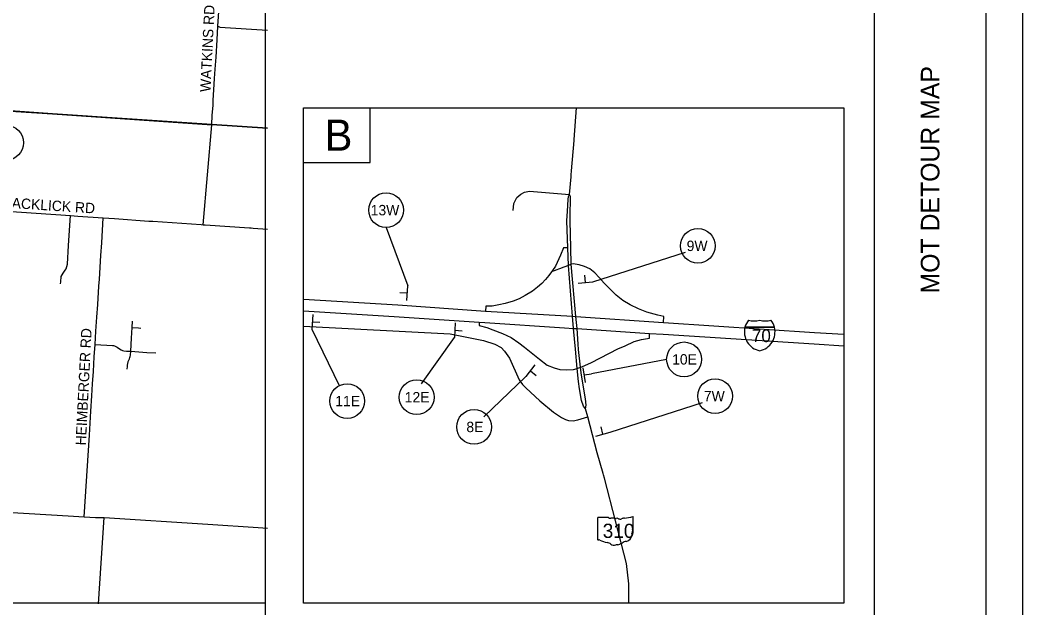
# Model space of a CAD drawing. Extents: x 1880545 to 1948545, y 79309 to 723051.
# Drawn here: x 1921540 to 1948545, y 691027 to 706870 of the extents above; entities that cross this region are included whole.
import ezdxf

# ---------------------------------------------------------------- set-up
doc = ezdxf.new("R2010")
doc.units = 0
for name, color, linetype in [('GM_X_County', 7, 'Continuous'), ('GM_X_County_Road', 7, 'Continuous'), ('GM_X_Interchange_Ramps', 7, 'Continuous'), ('GM_X_Interstate_Route', 7, 'Continuous'), ('GM_X_Interstate_Shield', 7, 'Continuous'), ('GM_X_State_Route', 7, 'Continuous'), ('GM_X_State_Shield', 7, 'Continuous'), ('GM_X_Township', 7, 'Continuous'), ('GM_X_Township_Road', 7, 'Continuous'), ('SH_Border', 7, 'Continuous'), ('SH_Cut_Line', 7, 'Continuous'), ('SH_Data', 7, 'Continuous'), ('SH_Text', 7, 'Continuous')]:
    doc.layers.add(name, color=color, linetype=linetype)

msp = doc.modelspace()

# ---------------------------------------------------------------- linework, layer by layer
at = {"layer": 'GM_X_County'}
msp.add_lwpolyline([(1921285, 704420), (1922414, 704344), (1926703, 704052), (1928206, 703952)], dxfattribs=at)
at = {"layer": 'GM_X_County_Road'}
for points in [[(1926867, 706707), (1926885, 706967), (1927000, 708778), (1927002, 708804)], [(1926704, 704049), (1926716, 704303), (1926736, 704569), (1926742, 704707), (1926762, 704992), (1926780, 705293), (1926797, 705544), (1926819, 705870), (1926849, 706332), (1926867, 706707)], [(1918344, 701901), (1920647, 701753), (1922902, 701601), (1923097, 701588), (1923778, 701542), (1924079, 701522), (1925008, 701454), (1925058, 701452), (1925112, 701448), (1926417, 701359), (1926469, 701355), (1926521, 701352), (1927717, 701271), (1927760, 701268), (1927820, 701264), (1928206, 701237)]]:
    msp.add_lwpolyline(points, dxfattribs=at)
at = {"layer": 'GM_X_Interchange_Ramps'}
for points in [[(1936289, 700732), (1936172, 700733), (1936094, 700533), (1935957, 700241), (1935879, 700117), (1935780, 699982), (1935689, 699875), (1935588, 699772), (1935470, 699667), (1935336, 699567), (1935137, 699445), (1934975, 699360), (1934821, 699294), (1934601, 699227), (1934428, 699194), (1934256, 699163), (1934079, 699159), (1934073, 699027)], [(1936384, 700292), (1936307, 700258), (1936183, 700212), (1936065, 700169), (1935970, 700132), (1935905, 700102), (1935879, 700117)], [(1938865, 698717), (1938871, 698882), (1938712, 698918), (1938417, 698999), (1938189, 699088), (1937965, 699195), (1937768, 699312), (1937589, 699455), (1937271, 699782), (1937132, 699936), (1937016, 700058), (1936886, 700162), (1936738, 700230), (1936597, 700270), (1936431, 700299), (1936384, 700292)], [(1933904, 698726), (1933898, 698642), (1934113, 698582), (1934268, 698520), (1934532, 698426), (1934760, 698314), (1934970, 698175), (1935123, 698054)], [(1936627, 697514), (1936663, 697527), (1936927, 697645), (1937634, 698006), (1937836, 698091), (1938079, 698207), (1938271, 698260), (1938485, 698301), (1938493, 698422)], [(1935123, 698054), (1935529, 697732), (1935735, 697567), (1935925, 697496), (1936075, 697455), (1936247, 697444), (1936445, 697457), (1936540, 697478), (1936627, 697514)]]:
    msp.add_lwpolyline(points, dxfattribs=at)
at = {"layer": 'GM_X_Interstate_Route'}
for points in [[(1929171, 699347), (1931715, 699191), (1934073, 699027), (1936416, 698889), (1936506, 698883), (1938865, 698717), (1942936, 698453), (1943726, 698404)], [(1929171, 699033), (1931612, 698884), (1933904, 698726), (1934059, 698717), (1936199, 698576)], [(1936199, 698576), (1936444, 698560), (1936540, 698554), (1938493, 698422), (1938854, 698403), (1942925, 698140), (1943726, 698088)]]:
    msp.add_lwpolyline(points, dxfattribs=at)
at = {"layer": 'GM_X_Interstate_Shield'}
for p, q in [((1941060, 698592), (1941853, 698592)), ((1941853, 698592), (1941060, 698592)), ((1941853, 698592), (1941060, 698592))]:
    msp.add_line(p, q, dxfattribs=at)
for centre, start, end in [((1941560, 698465), 141.669, 165.8066), ((1941306, 699278), 253.0091, 286.9909), ((1941607, 699278), 253.0091, 286.9909), ((1941353, 698465), 14.1934, 38.331), ((1941560, 698465), 165.8066, 258.463), ((1941353, 698465), 281.537, 14.1934)]:
    msp.add_arc(centre, 516, start, end, dxfattribs=at)
at = {"layer": 'GM_X_State_Route'}
for p, q in [((1936393, 702809), (1936461, 703622)), ((1936339, 702169), (1936380, 702648)), ((1936826, 696180), (1936768, 696393)), ((1937249, 694616), (1937240, 694646))]:
    msp.add_line(p, q, dxfattribs=at)
for points in [[(1936461, 703622), (1936463, 703655), (1936519, 704501)], [(1936380, 702648), (1936384, 702696), (1936393, 702809)], [(1936540, 697478), (1936492, 698002), (1936444, 698560), (1936416, 698889), (1936307, 700258), (1936289, 700732), (1936267, 701463), (1936279, 701716), (1936296, 702031), (1936308, 702111), (1936339, 702169)], [(1936570, 698134), (1936540, 698554), (1936506, 698883), (1936384, 700292), (1936368, 700730), (1936352, 701461), (1936354, 701698), (1936365, 701967), (1936359, 702111), (1936339, 702169)], [(1936627, 697514), (1936580, 697994), (1936570, 698134)], [(1936768, 696393), (1936714, 696466), (1936662, 696620), (1936604, 696936), (1936575, 697129), (1936540, 697478)], [(1936768, 696393), (1936780, 696490), (1936766, 696664), (1936709, 696980), (1936650, 697365), (1936627, 697514)], [(1937240, 694646), (1937081, 695211), (1936826, 696180)], [(1937935, 691152), (1937936, 691165), (1937936, 691675), (1937868, 692227), (1937274, 694524), (1937249, 694616)], [(1921174, 693612), (1921784, 693573), (1922832, 693507), (1923267, 693480), (1923569, 693461), (1923801, 693461), (1926597, 693281), (1927949, 693195), (1928206, 693179)]]:
    msp.add_lwpolyline(points, dxfattribs=at)
at = {"layer": 'GM_X_State_Shield'}
for p, q in [((1937093, 693454), (1937093, 692873)), ((1937382, 693464), (1937102, 693464)), ((1938050, 693175), (1938050, 693479)), ((1938050, 693175), (1938050, 693175))]:
    msp.add_line(p, q, dxfattribs=at)
for centre, major_axis, start_param, end_param in [((1937709, 694256), (1015, 0), 4.814394, 5.042369), ((1938039, 693480), (10.7, 0), 6.141152, 7.989035), ((1937104, 693455), (11.1, 0), 1.712693, 3.28349), ((1937449, 693532), (108, 0), 4.042523, 4.731795), ((1937485, 693138), (386, 0), 1.404758, 1.657858), ((1937573, 693458), (31, 0), 3.836095, 5.185415), ((1937618, 693391), (64.5, 0), 0.950623, 2.079405), ((1937701, 693483), (77.6, 0), 4.081561, 5.145723), ((1937838, 693287), (204, 0), 1.699011, 2.107814), ((1937766, 693009), (254, 0), 5.101752, 6.440018), ((1938088, 693047), (72, 0), 2.387724, 3.262537), ((1938047, 693152), (16.5, 0), 1.883978, 3.671073), ((1937942, 693114), (99, 0), 5.934695, 6.695948), ((1938038, 693173), (11.4, 0), 5.05454, 6.418171), ((1937104, 692872), (11.2, 0), 3.00124, 4.508301), ((1937106, 692931), (85.4, 0), 4.665946, 4.897461), ((1937123, 692839), (30.8, 0), 0.519207, 1.627899), ((1937512, 693362), (733, 0), 4.195997, 4.488961), ((1937293, 692612), (229, 0), 0.823519, 1.323587), ((1937541, 692837), (146, 0), 4.026481, 4.996735), ((1937625, 692636), (120, 0), 1.495662, 1.94098), ((1937636, 692793), (77.5, 0), 4.691044, 5.507374), ((1937706, 692737), (21.8, 0), 1.147584, 2.315152), ((1937697, 692817), (82, 0), 4.937069, 5.64225), ((1937873, 692710), (139, 0), 1.647645, 2.488434)]:
    msp.add_ellipse(centre, major_axis=major_axis, ratio=0.8, start_param=start_param, end_param=end_param, dxfattribs=at)
at = {"layer": 'GM_X_Township'}
for points in [[(1912324, 691136), (1912347, 691452), (1912503, 694180), (1912537, 694689), (1913032, 702200), (1913213, 704931), (1917683, 704648), (1918575, 704596), (1920102, 704498), (1921285, 704420), (1922414, 704344), (1926703, 704052), (1928206, 703952)], [(1928206, 703952), (1926703, 704052), (1922414, 704344), (1921285, 704420)]]:
    msp.add_lwpolyline(points, dxfattribs=at)
at = {"layer": 'GM_X_Township_Road'}
for p, q in [((1926469, 701355), (1926704, 704049)), ((1923656, 691136), (1923801, 693461))]:
    msp.add_line(p, q, dxfattribs=at)
for points in [[(1926704, 704049), (1926716, 704303), (1926736, 704569), (1926742, 704707), (1926762, 704992), (1926780, 705293), (1926797, 705544), (1926819, 705870), (1926849, 706332), (1926867, 706707)], [(1926867, 706707), (1926883, 706693), (1926906, 706685), (1926917, 706682), (1928206, 706601)], [(1921286, 704417), (1922415, 704341), (1926704, 704049)], [(1934816, 701737), (1934840, 701930), (1934914, 702085), (1935021, 702179), (1935127, 702233), (1935258, 702257), (1936339, 702169)], [(1922633, 699762), (1922636, 699812), (1922646, 699962), (1922701, 700045), (1922757, 700128), (1922782, 700164), (1922815, 700287), (1922847, 700792), (1922902, 701601)], [(1923267, 693480), (1923410, 695679), (1923445, 696332), (1923469, 696743), (1923492, 697070), (1923513, 697397), (1923538, 697790), (1923561, 698131), (1923583, 698486), (1923608, 698862), (1923630, 699205), (1923660, 699695), (1923676, 699890), (1923716, 700524), (1923738, 700867), (1923778, 701542)], [(1924426, 697460), (1924432, 697533), (1924437, 697586), (1924439, 697603), (1924441, 697619), (1924444, 697634), (1924449, 697651), (1924455, 697667), (1924487, 697741), (1924499, 697772), (1924507, 697804), (1924512, 697836), (1924519, 697944), (1924542, 698295), (1924560, 698582), (1924571, 698754)], [(1929171, 698624), (1933123, 698416), (1934019, 698232), (1934321, 698137), (1934492, 698046), (1934580, 697943), (1934670, 697823), (1934718, 697755), (1934978, 697176), (1935073, 697045), (1935156, 696957), (1935532, 696608), (1935907, 696299), (1936123, 696158), (1936231, 696108), (1936308, 696083), (1936437, 696073), (1936555, 696093), (1936826, 696180)], [(1924560, 698582), (1924730, 698572), (1924796, 698570)], [(1923561, 698131), (1924026, 698100), (1924059, 698096), (1924085, 698089)], [(1924085, 698089), (1924100, 698084), (1924121, 698075), (1924158, 698052), (1924220, 698007), (1924261, 697982), (1924298, 697966), (1924334, 697959), (1924404, 697951), (1924519, 697944), (1924954, 697915), (1925200, 697899)]]:
    msp.add_lwpolyline(points, dxfattribs=at)
at = {"layer": 'SH_Border'}
msp.add_line((1944545, 680051), (1944545, 722051), dxfattribs=at)
msp.add_lwpolyline([(1883545, 722051), (1947545, 722051), (1947545, 680051), (1883545, 680051)], close=True, dxfattribs=at)
at = {"layer": 'SH_Cut_Line'}
msp.add_lwpolyline([(1880545, 679051), (1948545, 679051), (1948545, 723051), (1880545, 723051)], close=True, dxfattribs=at)
at = {"layer": 'SH_Text'}
for p, q in [((1931395, 701280), (1931978, 699708)), ((1936965, 699812), (1939455, 700611)), ((1936766, 699795), (1936749, 699994)), ((1931954, 699309), (1931978, 699708)), ((1936567, 699777), (1936965, 699812)), ((1931966, 699509), (1931766, 699521)), ((1929425, 698937), (1929400, 698538)), ((1929413, 698738), (1929612, 698726)), ((1933258, 698710), (1933234, 698311)), ((1929400, 698538), (1930131, 697018)), ((1933246, 698510), (1933446, 698498)), ((1932345, 697064), (1933234, 698311)), ((1935405, 697575), (1935157, 697262)), ((1938951, 697726), (1936924, 697335)), ((1935281, 697419), (1935438, 697294)), ((1936696, 697502), (1936756, 697107)), ((1936726, 697305), (1936924, 697335)), ((1934026, 696181), (1935157, 697262)), ((1937428, 695762), (1939917, 696562)), ((1937041, 695660), (1937428, 695762)), ((1937235, 695711), (1937184, 695905)), ((1928141, 691152), (1928141, 687581))]:
    msp.add_line(p, q, dxfattribs=at)
for points in [[(1884490, 720381), (1928141, 720381), (1928141, 691152), (1884490, 691152)], [(1929171, 704501), (1943726, 704501), (1943726, 691152), (1929171, 691152)]]:
    msp.add_lwpolyline(points, close=True, dxfattribs=at)
msp.add_lwpolyline([(1929171, 703035), (1930971, 703035), (1930971, 704501)], dxfattribs=at)
for centre in [(1921168, 703565), (1931395, 701748), (1939792, 700785), (1939419, 697726), (1930348, 696603), (1932219, 696707), (1940254, 696735), (1933765, 695905)]:
    msp.add_circle(centre, 468, dxfattribs=at)

# ---------------------------------------------------------------- texts
at = {"layer": 'GM_X_Interstate_Shield'}
msp.add_text('70', height=343.8, dxfattribs=at).set_placement((1941245, 698192))
at = {"layer": 'GM_X_State_Shield'}
msp.add_text('310', height=382.9, dxfattribs=at).set_placement((1937229, 692914))
at = {"layer": 'SH_Data'}
msp.add_text('MOT DETOUR MAP', height=500, rotation=90, dxfattribs=at).set_placement((1946295, 699501))
at = {"layer": 'SH_Text'}
for s, rotation, p in [('WATKINS RD', 87.1395, (1926665, 704923)), ('BLACKLICK RD', 356.2172, (1920851, 701834)), ('HEIMBERGER RD', 87.1395, (1923311, 695402))]:
    msp.add_text(s, height=280, rotation=rotation, dxfattribs=at).set_placement(p)
for s, height, p in [('B', 840, (1929740, 703348)), ('13W', 280, (1930982, 701608)), ('9W', 280, (1939490, 700645)), ('10E', 280, (1939099, 697586)), ('11E', 280, (1930029, 696463)), ('12E', 280, (1931899, 696567)), ('7W', 280, (1939953, 696595)), ('8E', 280, (1933558, 695765))]:
    msp.add_text(s, height=height, dxfattribs=at).set_placement(p)

doc.saveas('drawing.dxf')
